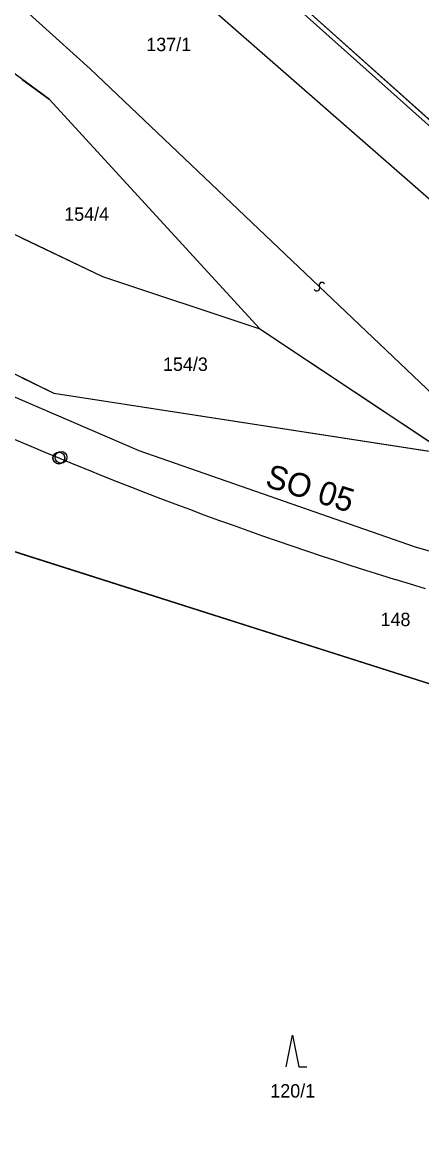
# Model space of a CAD drawing. Extents: x -792659 to -786947, y -1118170 to -1109641.
# Drawn here: x -789667.2 to -789641.9, y -1114315.8 to -1114245.3 of the extents above; entities that cross this region are included whole.
import ezdxf

# ---------------------------------------------------------------- set-up
doc = ezdxf.new("R2010")
doc.units = 0
doc.layers.add('1', color=7, linetype='Continuous')

# ---------------------------------------------------------------- blocks, each defined once
blk = doc.blocks.new('Z30801')
at = {"layer": '1'}
for p, q in [((-0.8, 0), (0, 4)), ((0, 4), (0.8, 0)), ((0.8, 0), (1.8, 0))]:
    blk.add_line(p, q, dxfattribs=at)

msp = doc.modelspace()

# ---------------------------------------------------------------- linework, layer by layer
at = {"layer": '1'}
for p, q in [((-789653.29, -1114241.26), (-789626.24, -1114265.44)), ((-789653.09, -1114241.036), (-789626.04, -1114265.216)), ((-789656.61, -1114243.22), (-789631.32, -1114265.33)), ((-789662.93, -1114248.27), (-789667.235, -1114244.365)), ((-789665.52, -1114250.19), (-789670.47, -1114246.55)), ((-789627.07, -1114282.33), (-789662.93, -1114248.27)), ((-789627.07, -1114282.33), (-789662.93, -1114248.27)), ((-789667.235, -1114248.929), (-789665.52, -1114250.19)), ((-789665.52, -1114250.19), (-789652.15, -1114264.75)), ((-789667.235, -1114267.853), (-789691.28, -1114256.01)), ((-789671.17, -1114257.11), (-789662.15, -1114261.44)), ((-789667.235, -1114258.999), (-789662.15, -1114261.44)), ((-789662.15, -1114261.44), (-789652.15, -1114264.75)), ((-789662.15, -1114261.44), (-789652.15, -1114264.75)), ((-789652.15, -1114264.75), (-789640.19, -1114272.7)), ((-789667.235, -1114267.853), (-789665.23, -1114268.84)), ((-789667.235, -1114267.853), (-789667.235, -1114267.853)), ((-789665.23, -1114268.84), (-789640.19, -1114272.7)), ((-789672.68, -1114277.31), (-789667.235, -1114279.043)), ((-789667.235, -1114279.043), (-789641.23, -1114287.32))]:
    msp.add_line(p, q, dxfattribs=at)
for points in [[(-789674.01, -1114222.232), (-789653.09, -1114241.037), (-789626.089, -1114265.173), (-789585.645, -1114277.759), (-789547.205, -1114285.569), (-789509.71, -1114297.224), (-789475.119, -1114308.284), (-789456.079, -1114314.364), (-789451.572, -1114315.806)], [(-789534.18, -1114315.38), (-789561.38, -1114306.6), (-789562.235, -1114306.385), (-789592.9, -1114298.82), (-789600.46, -1114294.39), (-789619.3, -1114290.36), (-789624.34, -1114291.37), (-789641.23, -1114287.32), (-789672.68, -1114277.31), (-789724.61, -1114250.58), (-789729.37, -1114244.66), (-789729.37, -1114234.086), (-789721.98, -1114237.82), (-789717.72, -1114240.35), (-789691.28, -1114256.01), (-789665.23, -1114268.84), (-789640.19, -1114272.7), (-789627.07, -1114282.33), (-789607.19, -1114286.63), (-789603.91, -1114286.39), (-789562.235, -1114295.417), (-789557.19, -1114296.51), (-789534.19, -1114304.37)], [(-789729.37, -1114235.184), (-789723.862, -1114237.997), (-789721.431, -1114240.246), (-789715.579, -1114243.503), (-789712.528, -1114244.57), (-789693.799, -1114256.222), (-789674.69, -1114266.079), (-789667.235, -1114269.285), (-789659.833, -1114272.468), (-789642.291, -1114278.583), (-789637.658, -1114279.919), (-789636.672, -1114276.495), (-789634.932, -1114276.106), (-789616.443, -1114277.002), (-789610.603, -1114282.06), (-789604.228, -1114283.252)], [(-789729.37, -1114235.184), (-789723.862, -1114237.997), (-789721.431, -1114240.246), (-789715.579, -1114243.503), (-789712.528, -1114244.57), (-789693.799, -1114256.222), (-789674.69, -1114266.079), (-789667.235, -1114269.285), (-789659.833, -1114272.468), (-789642.291, -1114278.583), (-789637.658, -1114279.919), (-789636.672, -1114276.495), (-789634.932, -1114276.106), (-789616.443, -1114277.002), (-789610.603, -1114282.06), (-789604.228, -1114283.252)], [(-789652.15, -1114264.75), (-789640.19, -1114272.7), (-789627.07, -1114282.33), (-789607.19, -1114286.63), (-789603.91, -1114286.39), (-789609.87, -1114279.55), (-789626.24, -1114265.44)], [(-789667.235, -1114269.285), (-789659.833, -1114272.468), (-789642.291, -1114278.583), (-789637.658, -1114279.919), (-789636.672, -1114276.495), (-789634.932, -1114276.106), (-789616.443, -1114277.002), (-789610.603, -1114282.06), (-789604.228, -1114283.252)], [(-789667.235, -1114269.285), (-789659.833, -1114272.468), (-789642.291, -1114278.583), (-789637.658, -1114279.919), (-789636.672, -1114276.495), (-789634.932, -1114276.106), (-789616.443, -1114277.002), (-789610.603, -1114282.06), (-789604.228, -1114283.252)], [(-789667.235, -1114269.285), (-789659.833, -1114272.468), (-789642.291, -1114278.583), (-789637.658, -1114279.919), (-789636.672, -1114276.495), (-789634.932, -1114276.106), (-789616.443, -1114277.002), (-789610.603, -1114282.06), (-789604.228, -1114283.252)], [(-789641.642, -1114281.246), (-789642.604, -1114280.953), (-789643.566, -1114280.656)], [(-789641.642, -1114281.246), (-789642.604, -1114280.953), (-789643.566, -1114280.656)], [(-789641.642, -1114281.246), (-789642.604, -1114280.953), (-789643.566, -1114280.656)], [(-789641.642, -1114281.246), (-789642.604, -1114280.953), (-789643.566, -1114280.656)]]:
    msp.add_lwpolyline(points, dxfattribs=at)
for centre in [(-789664.91, -1114272.94), (-789664.91, -1114272.95), (-789664.77, -1114272.9), (-789664.77, -1114272.9)]:
    msp.add_circle(centre, 0.375, dxfattribs=at)
for centre, radius, start, end in [((-789648.209, -1114261.99), 0.188, 27.58203, 207.58202), ((-789648.542, -1114262.164), 0.188, 207.58203, 27.58203), ((-789569.363, -1114041.922), 250, 245.50499, 252.7337), ((-789569.363, -1114041.922), 250, 245.50499, 252.7337), ((-789569.363, -1114041.922), 250, 245.50499, 252.7337), ((-789569.363, -1114041.922), 250, 245.50499, 252.7337)]:
    msp.add_arc(centre, radius, start, end, dxfattribs=at)

# ---------------------------------------------------------------- block references
at = {"layer": '1', "xscale": 0.5, "yscale": 0.5}
msp.add_blockref('Z30801', (-789650.075, -1114311.555), dxfattribs=at)

# ---------------------------------------------------------------- texts
at = {"layer": '1'}
for s, p in [('137/1', (-789659.36, -1114247.14)), ('154/4', (-789664.57, -1114257.9)), ('154/3', (-789658.3, -1114267.42)), ('148', (-789644.496, -1114283.607)), ('120/1', (-789651.49, -1114313.51))]:
    msp.add_text(s, height=0.85, dxfattribs=at).set_placement(p)
msp.add_text('SO 05', height=1.5, rotation=342.68106, dxfattribs=at).set_placement((-789651.89, -1114274.73))

doc.saveas('drawing.dxf')
